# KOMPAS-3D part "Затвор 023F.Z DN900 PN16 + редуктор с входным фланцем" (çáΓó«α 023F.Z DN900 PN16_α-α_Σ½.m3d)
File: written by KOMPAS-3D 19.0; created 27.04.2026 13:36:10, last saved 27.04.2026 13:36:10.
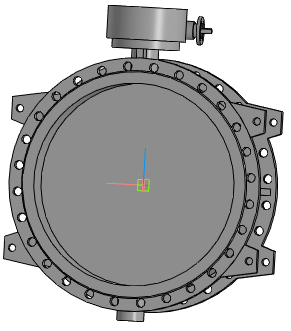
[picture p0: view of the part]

Document properties: Полное имя файла: ..\..\Затвор 023F.Z DN200-DN1600_редуктор с входным фланцем\Затвор 023F.Z DN900 PN16 + редуктор с входным фланцем.a3d

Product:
- Part/product: Затвор 023F.Z DN900 PN16 + редуктор с входным фланцем
    Масса: 1056.75

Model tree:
1. Операция без истории:1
